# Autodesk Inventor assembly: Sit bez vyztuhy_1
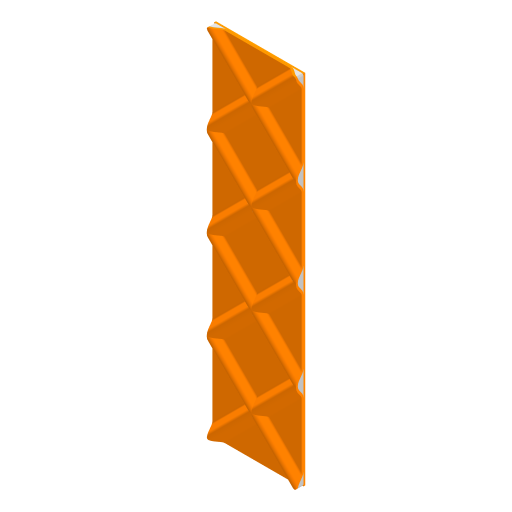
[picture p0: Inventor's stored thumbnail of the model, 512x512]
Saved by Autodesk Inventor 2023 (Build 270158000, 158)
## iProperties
Created: 2025-03
Part Number: Sit bez vyztuhy_1
Document SubType Name: Assembly
Designer: tomik
Author: tomik
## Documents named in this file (4)
- C:\Users\tomik\Desktop\Diplomka\Struktury\Desky\Struktury_20.3\Sit bez vyztuhy\Sit bez vyztuhy_1.iam
- C:\Users\tomik\Desktop\Diplomka\Struktury\Desky\Struktury_20.3\Sit bez vyztuhy\Spodni tkanina 50x200.ipt
- C:\Users\tomik\Desktop\Diplomka\Struktury\Desky\Struktury_20.3\Sit bez vyztuhy\Sit bez vyztuhy_nova.ipt
- C:\Users\tomik\Desktop\Diplomka\Struktury\Desky\Struktury_20.3\Sit bez vyztuhy\Horni_tkanina.ipt
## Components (3 placed, 3 different names)
1. Spodni tkanina 50x200:1 — Proti sobě:1, Proti sobě:2, Stejný směr:1, Proti sobě:3, Proti sobě:4, Proti sobě:5
2. Sit bez vyztuhy_nova:1 — Proti sobě:3, Proti sobě:4, Proti sobě:5, Proti sobě:6, Proti sobě:7
3. Horni_tkanina:1 — Proti sobě:6, Proti sobě:7
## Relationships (8: Mate 7, Flush 1)
- Proti sobě:1 [Mate]: Spodni tkanina 50x200:1
- Proti sobě:2 [Mate]: Spodni tkanina 50x200:1
- Stejný směr:1 [Flush]: Spodni tkanina 50x200:1
- Proti sobě:3 [Mate]: Spodni tkanina 50x200:1 ↔ Sit bez vyztuhy_nova:1
- Proti sobě:4 [Mate]: Spodni tkanina 50x200:1 ↔ Sit bez vyztuhy_nova:1
- Proti sobě:5 [Mate]: Spodni tkanina 50x200:1 ↔ Sit bez vyztuhy_nova:1
- Proti sobě:6 [Mate]: Sit bez vyztuhy_nova:1 ↔ Horni_tkanina:1
- Proti sobě:7 [Mate]: Sit bez vyztuhy_nova:1 ↔ Horni_tkanina:1
